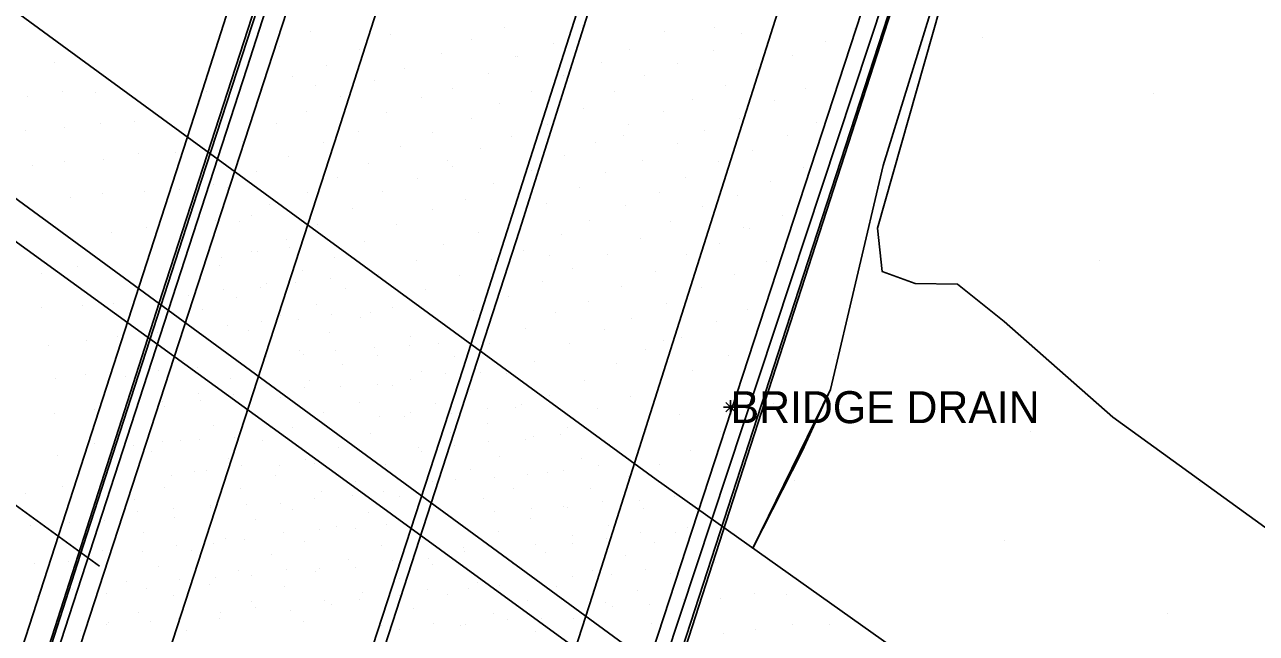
# Model space of a CAD drawing. Extents: x 0 to 1739264, y 0 to 465304.
# Drawn here: x 1738835.1 to 1738904.4, y 464692.7 to 464726.9 of the extents above; entities that cross this region are included whole.
import ezdxf

# ---------------------------------------------------------------- set-up
doc = ezdxf.new("R2010")
doc.units = 0
for name, color, linetype in [('Default', 7, 'Continuous'), ('S_Ground_SpotElevation', 7, 'Continuous'), ('S_Misc_MiscItems', 7, 'Continuous'), ('S_Terrain_Boundary', 7, 'Continuous'), ('S_Terrain_Holes', 7, 'Continuous'), ('S_Terrain_Imported_Contours', 7, 'Continuous'), ('S_Terrain_Low_Points', 7, 'Continuous'), ('S_Terrain_Major_Contours_Label', 7, 'Continuous'), ('S_Terrain_Minor_Contours', 7, 'Continuous'), ('S_Terrain_Spots', 7, 'Continuous'), ('S_Terrain_Triangles', 7, 'Continuous'), ('S_Terrain_Voids', 7, 'Continuous'), ('S_Text', 7, 'Continuous')]:
    doc.layers.add(name, color=color, linetype=linetype)

# ---------------------------------------------------------------- blocks, each defined once
blk = doc.blocks.new('POINT_DISPLAY')
at = {"layer": 'Default'}
blk.add_line((0, 0), (0, 0), dxfattribs=at)

msp = doc.modelspace()

# ---------------------------------------------------------------- linework, layer by layer
at = {"layer": 'S_Misc_MiscItems'}
for p, q in [((1738875.090081, 464705.125119), (1738874.565919, 464705.649281)), ((1738875.090081, 464705.649281), (1738874.565919, 464705.125119)), ((1738874.828, 464705.780125), (1738874.828, 464704.994275)), ((1738875.220925, 464705.3872), (1738874.435075, 464705.3872))]:
    msp.add_line(p, q, dxfattribs=at)
at = {"layer": 'S_Terrain_Boundary'}
msp.add_lwpolyline([(1739240.087209, 464422.512092), (1739204.20461, 464448.975806), (1739151.98821, 464486.847297), (1739077.545202, 464540.718299), (1739036.299199, 464570.587592), (1738998.913701, 464597.936805), (1738915.898401, 464658.026801), (1738879.6822, 464684.091499), (1738826.038202, 464723.403098), (1738785.838697, 464752.297202), (1738730.174596, 464792.732001), (1738678.937795, 464830.008598), (1738622.825002, 464870.7028), (1738578.496206, 464902.7599), (1738526.77361, 464940.2817), (1738487.876485, 464968.875201)], dxfattribs=at)
at = {"layer": 'S_Terrain_Holes'}
msp.add_lwpolyline([(1738492.982015, 464976.242099), (1738514.851095, 464960.0815), (1738563.791494, 464924.7685), (1738624.996999, 464880.339801), (1738673.015905, 464845.222999), (1738705.323293, 464821.628898), (1738726.980504, 464805.7443), (1738753.122999, 464787.077293), (1738791.7562, 464758.973594), (1738812.206201, 464744.064307), (1738838.2751, 464724.973701), (1738870.6467, 464701.313407), (1738896.6608, 464682.840995), (1738936.578298, 464654.121894), (1738968.041097, 464631.189491), (1739001.793905, 464606.514411), (1739033.507696, 464583.63401), (1739053.896306, 464568.752204), (1739082.668798, 464547.766914), (1739122.612798, 464519.166297), (1739150.551503, 464498.742286), (1739185.599386, 464473.337501), (1739245.296285, 464429.765205)], dxfattribs=at)
at = {"layer": 'S_Terrain_Imported_Contours'}
msp.add_line((1738839.318, 464696.438194), (1738826.649499, 464705.649802), dxfattribs=at)
for points in [[(1738486.786886, 464967.328601), (1738511.286214, 464949.6202), (1738544.3709, 464925.4377), (1738582.310689, 464897.903999), (1738620.877294, 464869.822101), (1738659.468999, 464841.841804), (1738694.403493, 464816.496497), (1738735.406698, 464786.775001), (1738771.038297, 464760.946204), (1738812.0253, 464731.080299), (1738852.9921, 464701.379905), (1738891.8019, 464673.129615), (1738927.017999, 464647.615485), (1738972.948697, 464614.396308), (1739021.394994, 464579.194892), (1739065.901006, 464546.893897), (1739094.060003, 464526.5232), (1739126.956991, 464502.811591), (1739168.727712, 464472.415687), (1739212.603414, 464440.554298), (1739239.28951, 464421.227393)], [(1738861.917132, 464749.554455), (1738852.728099, 464720.865302), (1738834.137899, 464663.640296), (1738810.806299, 464591.494392), (1738798.57878, 464553.775144)], [(1738807.560265, 464547.101191), (1738818.883699, 464581.650611), (1738840.7733, 464649.227912), (1738859.7717, 464707.561698), (1738871.099421, 464743.042961)], [(1738871.2811, 464741.761298), (1738862.9528, 464715.336097), (1738835.861902, 464631.717414), (1738814.1443, 464564.731208), (1738808.177672, 464546.642409)], [(1738816.833754, 464540.526168), (1738828.844899, 464576.996803), (1738841.383399, 464615.664314), (1738851.1298, 464645.487891), (1738867.0642, 464694.79), (1738880.224773, 464736.284008)]]:
    msp.add_lwpolyline(points, dxfattribs=at)
at = {"layer": 'S_Terrain_Low_Points'}
for points in [[(1738792.605864, 464561.753915), (1738808.947702, 464611.187598), (1738829.7665, 464675.843208), (1738844.662601, 464721.815192), (1738854.169417, 464751.567291)], [(1738856.4555, 464747.969505), (1738838.244399, 464692.009101), (1738826.647699, 464655.847602), (1738824.734399, 464649.915199), (1738812.578801, 464612.657905), (1738795.808896, 464560.843085)], [(1738882.8352, 464729.589896), (1738865.96384, 464677.988066), (1738852.7233, 464636.911414), (1738851.7415, 464633.401588)], [(1738885.748688, 464729.001744), (1738886.292251, 464728.345413), (1738883.4181, 464718.991294), (1738880.4518, 464706.388297), (1738878.8439, 464702.915), (1738876.083852, 464697.452527)]]:
    msp.add_lwpolyline(points, dxfattribs=at)
at = {"layer": 'S_Terrain_Major_Contours_Label'}
for points in [[(1738793.029831, 464557.898451), (1738803.9838, 464591.509406), (1738812.589898, 464618.183295), (1738822.305799, 464648.240607), (1738833.2133, 464681.803199), (1738842.84, 464711.786903), (1738850.196, 464734.470405), (1738856.340829, 464753.508813)], [(1738885.395159, 464732.452095), (1738884.2943, 464729.028999), (1738875.3401, 464701.327995), (1738857.6966, 464646.653999), (1738844.752799, 464606.659614), (1738829.9694, 464560.926002), (1738822.141572, 464536.77828)]]:
    msp.add_lwpolyline(points, dxfattribs=at)
at = {"layer": 'S_Terrain_Minor_Contours'}
msp.add_line((1738866.688, 464677.65191), (1738883.905735, 464729.730556), dxfattribs=at)
msp.add_lwpolyline([(1738835.762039, 464687.932576), (1738847.598619, 464724.443536), (1738855.882145, 464750.170609)], dxfattribs=at)
at = {"layer": 'S_Terrain_Spots'}
msp.add_lwpolyline([(1738876.083852, 464697.452527), (1738880.4518, 464706.388297), (1738883.4181, 464718.991294), (1738886.292251, 464728.345413), (1738885.754413, 464729.003456)], dxfattribs=at)
at = {"layer": 'S_Terrain_Triangles'}
for points in [[(1738793.143077, 464557.8143), (1738794.925598, 464563.221652), (1738800.413936, 464580.303997), (1738804.057897, 464591.416999), (1738810.426301, 464610.960395), (1738818.2273, 464635.285011), (1738828.789701, 464667.726112), (1738838.3903, 464697.576408), (1738845.034101, 464718.107597), (1738853.3717, 464743.659003), (1738856.448989, 464753.432112)], [(1738885.339743, 464732.493165), (1738884.4636, 464729.823402), (1738878.6737, 464712.005698), (1738871.4064, 464689.647605), (1738862.8085, 464662.946113), (1738850.8758, 464625.801398), (1738841.409499, 464596.833595), (1738830.533101, 464562.882606), (1738822.877599, 464539.516792), (1738822.019587, 464536.864414)]]:
    msp.add_lwpolyline(points, dxfattribs=at)
at = {"layer": 'S_Terrain_Voids'}
msp.add_lwpolyline([(1739013.416204, 464694.269599), (1738992.965101, 464701.439201), (1738965.663099, 464709.157493), (1738950.283803, 464712.266593), (1738937.222402, 464707.762901), (1738926.393098, 464697.901405), (1738919.4708, 464694.428107), (1738904.882501, 464698.625404), (1738896.325099, 464704.816901), (1738890.220901, 464710.206306), (1738887.592599, 464712.305305), (1738885.2014, 464712.349006), (1738883.3513, 464713.029807), (1738883.0827, 464715.465797), (1738888.3805, 464734.110099), (1738896.6555, 464759.168403), (1738900.4475, 464763.281593), (1738908.0099, 464781.7947), (1738922.6662, 464824.5549), (1738935.930204, 464865.3283), (1738941.605104, 464883.875591)], dxfattribs=at)

# ---------------------------------------------------------------- block references
at = {"layer": 'S_Ground_SpotElevation'}
for p in [(1738851.179607, 464726.509392), (1738855.691402, 464726.355522), (1738862.131007, 464726.739616), (1738866.502605, 464726.874565), (1738871.1011, 464726.510368), (1738873.915299, 464726.747596), (1738875.412105, 464726.413872), (1738881.824397, 464726.691093), (1738849.444698, 464725.70861), (1738860.247996, 464726.066215), (1738864.852397, 464725.845085), (1738880.143001, 464725.964409), (1738889.020493, 464726.170879), (1738853.943706, 464725.52819), (1738858.583797, 464725.288566), (1738862.728299, 464725.105994), (1738862.8231, 464725.117668), (1738869.120799, 464725.542473), (1738873.846797, 464725.436577), (1738878.2886, 464725.153313), (1738836.769603, 464724.795803), (1738852.062007, 464724.60601), (1738856.474101, 464724.429985), (1738867.554195, 464724.78582), (1738871.831599, 464724.749687), (1738876.309795, 464724.395073), (1738850.187801, 464724.015983), (1738854.782298, 464723.794975), (1738861.199397, 464724.168388), (1738865.429805, 464724.061394), (1738869.991603, 464724.038566), (1738880.997295, 464724.23217), (1738835.254101, 464722.880001), (1738837.217388, 464723.139706), (1738839.120586, 464723.106701), (1738845.317094, 464723.150189), (1738848.490001, 464723.263603), (1738851.4472, 464723.516395), (1738852.876201, 464722.85778), (1738859.178706, 464723.346672), (1738863.619594, 464723.148613), (1738868.296596, 464723.178581), (1738874.525005, 464723.502922), (1738879.062099, 464723.305595), (1738898.626008, 464723.063519), (1738857.461406, 464722.796379), (1738861.799998, 464722.477409), (1738866.551799, 464722.17382), (1738872.693599, 464722.692802), (1738877.322505, 464722.64019), (1738850.976298, 464722.030388), (1738855.455699, 464721.945305), (1738860.261607, 464721.61541), (1738871.044704, 464722.040581), (1738875.313808, 464721.632683), (1738880.308699, 464721.944007), (1738835.138408, 464720.949398), (1738837.352306, 464721.104611), (1738839.398693, 464721.357205), (1738841.268291, 464721.448605), (1738849.293208, 464721.331474), (1738853.884105, 464720.911064), (1738858.0666, 464720.828667), (1738864.546001, 464721.276665), (1738869.059703, 464721.287285), (1738873.3334, 464720.977775), (1738879.685405, 464721.428703), (1738847.391307, 464720.331901), (1738851.893306, 464720.288505), (1738862.521098, 464720.609367), (1738867.229594, 464720.30468), (1738868.8017, 464720.668601), (1738871.831004, 464720.217522), (1738878.050304, 464720.664299), (1738841.485393, 464719.641201), (1738843.577404, 464719.722805), (1738849.956599, 464719.519279), (1738856.261607, 464720.066521), (1738860.745097, 464719.950615), (1738865.498302, 464719.547966), (1738876.053905, 464719.826591), (1738835.5312, 464718.97131), (1738837.33601, 464719.186505), (1738839.549999, 464719.352108), (1738854.477397, 464719.098564), (1738858.908, 464719.285193), (1738859.1972, 464718.904899), (1738863.645595, 464718.711906), (1738869.875102, 464719.248894), (1738874.138393, 464719.194267), (1738878.942699, 464718.882072), (1738848.168697, 464718.675102), (1738852.713405, 464718.291008), (1738857.213695, 464718.2658), (1738867.794704, 464718.614006), (1738872.307002, 464718.337517), (1738877.057994, 464718.083977), (1738839.461895, 464717.401104), (1738841.827801, 464717.498104), (1738843.825298, 464717.656399), (1738845.757213, 464717.943402), (1738846.5115, 464717.73809), (1738851.038798, 464717.468376), (1738855.249095, 464717.536491), (1738861.511394, 464717.993584), (1738866.305202, 464717.747185), (1738870.806102, 464717.477898), (1738875.240596, 464717.324089), (1738883.760194, 464717.70097), (1738837.704296, 464717.188198), (1738848.904704, 464716.820122), (1738859.927608, 464717.065117), (1738864.449702, 464716.82299), (1738868.929698, 464716.722771), (1738873.240199, 464716.679863), (1738847.872295, 464716.16), (1738853.557307, 464716.562919), (1738858.070598, 464716.524101), (1738862.421199, 464716.282768), (1738877.727397, 464716.18267), (1738841.970501, 464715.511898), (1738844.018291, 464715.691006), (1738845.862591, 464715.895199), (1738847.196101, 464715.859611), (1738851.587596, 464715.668205), (1738856.048793, 464715.665398), (1738860.629298, 464715.228508), (1738866.864497, 464715.908073), (1738871.434795, 464715.811088), (1738875.5377, 464715.513007), (1738875.903194, 464715.424309), (1738839.979686, 464715.188809), (1738849.833308, 464714.832085), (1738854.207194, 464714.7033), (1738865.318294, 464715.124382), (1738869.749904, 464714.860222), (1738874.214793, 464714.59832), (1738847.879207, 464714.168388), (1738848.184093, 464714.158612), (1738849.996013, 464714.387799), (1738858.687099, 464714.534294), (1738863.183406, 464714.225517), (1738864.6091, 464713.898001), (1738867.892802, 464713.959282), (1738872.320293, 464713.957573), (1738838.077404, 464713.283108), (1738842.054302, 464713.671398), (1738844.188488, 464713.780606), (1738846.052104, 464713.341484), (1738846.180401, 464713.831799), (1738852.539699, 464713.808281), (1738857.151393, 464713.627067), (1738861.345805, 464713.670769), (1738865.906505, 464713.205009), (1738876.831905, 464713.602714), (1738895.591599, 464713.632916), (1738836.069286, 464712.911511), (1738850.762706, 464713.079765), (1738852.302105, 464712.634808), (1738855.040294, 464712.868767), (1738859.550197, 464712.824272), (1738864.2653, 464712.472771), (1738870.574901, 464712.996513), (1738875.050304, 464712.868278), (1738846.276989, 464711.987408), (1738848.382305, 464712.097409), (1738848.729304, 464712.326774), (1738850.366985, 464712.381008), (1738853.176295, 464712.065605), (1738857.672298, 464711.997673), (1738868.666698, 464712.16552), (1738873.195094, 464712.147392), (1738838.389599, 464711.091198), (1738840.093487, 464711.21751), (1738844.329509, 464711.691403), (1738847.012508, 464711.567314), (1738851.530894, 464711.13781), (1738862.346004, 464711.633415), (1738866.849696, 464711.314323), (1738871.2382, 464711.239616), (1738836.059307, 464710.988903), (1738845.094096, 464710.894401), (1738849.489604, 464710.542595), (1738852.389904, 464710.6143), (1738853.999797, 464710.427666), (1738854.539287, 464710.736904), (1738855.814296, 464711.019707), (1738860.3464, 464710.850578), (1738864.950496, 464710.703972), (1738869.225993, 464710.385918), (1738875.787501, 464710.908989), (1738846.531109, 464709.963406), (1738847.6804, 464709.706108), (1738848.405987, 464710.230999), (1738850.505413, 464710.322811), (1738858.462505, 464710.167717), (1738863.270305, 464709.829521), (1738867.715297, 464709.759209), (1738874.039607, 464710.231804), (1738838.602703, 464709.139309), (1738840.344311, 464709.37991), (1738842.596203, 464709.594403), (1738852.246699, 464709.590263), (1738856.824596, 464709.370781), (1738871.0467, 464709.116095), (1738872.057002, 464709.328972), (1738836.461803, 464708.879208), (1738845.878398, 464708.905205), (1738850.587596, 464708.577019), (1738850.797497, 464708.333111), (1738852.601085, 464708.573208), (1738854.781109, 464708.718807), (1738854.9761, 464708.300712), (1738856.764995, 464708.836209), (1738858.399303, 464708.964504), (1738861.279796, 464708.952568), (1738865.7756, 464708.955009), (1738870.017894, 464708.617912), (1738874.729198, 464708.313164), (1738880.6297, 464708.374798), (1738844.019206, 464708.021416), (1738844.831402, 464707.613308), (1738848.571696, 464708.000908), (1738848.688396, 464708.228802), (1738852.984096, 464707.806206), (1738859.294597, 464708.219902), (1738863.780406, 464707.946403), (1738868.425807, 464707.855278), (1738836.8531, 464706.986111), (1738838.526104, 464707.200299), (1738840.783611, 464707.125012), (1738842.664196, 464707.430905), (1738846.662395, 464707.00811), (1738856.839, 464706.960507), (1738857.4183, 464707.407219), (1738858.809612, 464707.283306), (1738860.737194, 464707.317303), (1738862.238795, 464707.289299), (1738872.702205, 464707.443474), (1738850.828106, 464706.497906), (1738851.134303, 464706.896965), (1738852.876995, 464706.575009), (1738854.952099, 464706.669506), (1738855.784495, 464706.62957), (1738860.172801, 464706.385979), (1738866.617107, 464706.872002), (1738870.891093, 464706.82238), (1738875.344401, 464706.464165), (1738842.867992, 464705.684506), (1738844.898494, 464706.172722), (1738844.997814, 464705.783901), (1738846.845989, 464706.083798), (1738849.522304, 464705.905571), (1738853.962901, 464705.673515), (1738858.229304, 464705.58062), (1738863.074291, 464705.549298), (1738864.631801, 464706.030693), (1738869.209407, 464705.964165), (1738877.212901, 464705.574196), (1738836.789196, 464705.048199), (1738839.009014, 464705.241604), (1738840.83189, 464705.518505), (1738843.002299, 464705.432121), (1738847.575908, 464705.197197), (1738851.939006, 464705.069511), (1738855.098613, 464704.884411), (1738856.504802, 464704.835319), (1738856.805309, 464705.082699), (1738859.145397, 464705.0126), (1738861.132305, 464705.324307), (1738862.740794, 464705.363518), (1738867.318095, 464705.311882), (1738871.965495, 464704.998405), (1738845.709193, 464704.378776), (1738848.932689, 464704.226803), (1738850.171504, 464704.262199), (1738861.159007, 464704.487175), (1738865.664699, 464704.260612), (1738842.885113, 464703.467205), (1738843.857402, 464703.517692), (1738844.931011, 464703.578808), (1738846.9239, 464703.670712), (1738848.466807, 464703.529411), (1738854.5787, 464703.90728), (1738859.079295, 464703.937492), (1738861.230785, 464703.468502), (1738863.299206, 464703.5462), (1738863.761806, 464703.732414), (1738865.266704, 464703.85191), (1738870.118007, 464704.130607), (1738874.284007, 464704.023003), (1738891.716203, 464704.039471), (1738839.050915, 464703.324902), (1738841.218914, 464703.25021), (1738842.266795, 464702.873772), (1738852.771602, 464703.136406), (1738857.241985, 464703.114605), (1738857.4575, 464702.914116), (1738859.311199, 464703.217312), (1738868.030604, 464703.293388), (1738872.581905, 464702.976921), (1738836.951885, 464702.673809), (1738846.555904, 464702.511711), (1738847.288585, 464702.122509), (1738849.420208, 464702.093899), (1738850.904094, 464702.452812), (1738851.394787, 464702.21751), (1738855.403499, 464702.155022), (1738861.799403, 464702.613579), (1738866.422206, 464702.473381), (1738867.412914, 464702.102505), (1738870.831203, 464702.150688), (1738841.287395, 464701.479412), (1738843.378399, 464701.523709), (1738844.665996, 464701.755363), (1738845.359295, 464701.84251), (1738849.205699, 464701.518303), (1738860.165996, 464701.907402), (1738861.514995, 464701.450802), (1738863.417797, 464701.592098), (1738864.541606, 464701.704277), (1738865.450207, 464701.799511), (1738869.074107, 464701.479912), (1738837.244793, 464700.914105), (1738839.351299, 464701.051708), (1738842.985606, 464700.859794), (1738847.237804, 464700.798881), (1738853.733699, 464701.22448), (1738858.077693, 464701.189323), (1738859.355205, 464701.332897), (1738862.635799, 464700.79998), (1738866.968806, 464700.830192), (1738873.574199, 464701.241691), (1738878.438096, 464701.24992), (1738901.204896, 464701.149273), (1738835.172497, 464700.511608), (1738841.303996, 464700.177666), (1738851.442089, 464700.27351), (1738851.790706, 464700.631523), (1738853.553814, 464700.399502), (1738855.323406, 464700.659405), (1738856.196803, 464700.382011), (1738860.924998, 464700.250175), (1738867.611706, 464700.064511), (1738869.703594, 464700.1591), (1738871.696605, 464700.374199), (1738841.434307, 464699.533703), (1738843.501812, 464699.696499), (1738845.542995, 464699.833671), (1738845.579601, 464699.769299), (1738847.612407, 464699.919705), (1738849.503795, 464699.94421), (1738850.158794, 464699.602775), (1738854.428905, 464699.461784), (1738861.559795, 464699.512707), (1738863.631298, 464699.689404), (1738865.403102, 464699.79998), (1738865.657207, 464699.759701), (1738869.924602, 464699.689995), (1738835.449901, 464698.717709), (1738837.628185, 464698.919903), (1738839.627086, 464699.021206), (1738843.561397, 464699.189323), (1738848.103999, 464699.073173), (1738852.628505, 464698.65258), (1738855.4575, 464698.803005), (1738859.119899, 464699.251213), (1738863.576594, 464699.095695), (1738867.932597, 464698.742912), (1738872.377101, 464698.603264), (1738841.799297, 464698.319694), (1738846.427394, 464697.98632), (1738847.45869, 464697.917309), (1738849.650402, 464698.357403), (1738851.719707, 464698.4781), (1738853.7057, 464698.557507), (1738857.227306, 464698.339897), (1738861.794994, 464698.388115), (1738865.918193, 464698.182121), (1738867.841686, 464698.017605), (1738869.764385, 464698.308209), (1738871.747509, 464698.334011), (1738839.483104, 464697.32481), (1738840.032497, 464697.477714), (1738841.761394, 464697.2617), (1738843.672313, 464697.580898), (1738844.498103, 464697.296318), (1738845.738811, 464697.691204), (1738850.871898, 464697.843803), (1738855.192104, 464697.577873), (1738859.809505, 464697.50872), (1738859.855297, 464697.267803), (1738863.871807, 464697.674298), (1738865.92979, 464697.739605), (1738870.557994, 464697.792595), (1738890.263001, 464697.900128), (1738835.651012, 464696.597805), (1738837.559612, 464696.686001), (1738848.968898, 464697.087273), (1738853.351695, 464696.807304), (1738855.803386, 464696.764309), (1738857.807415, 464696.879208), (1738858.064998, 464696.555412), (1738862.547603, 464696.569206), (1738864.411998, 464697.194816), (1738868.893794, 464697.032585), (1738874.002697, 464696.634609), (1738842.621501, 464696.398491), (1738847.163402, 464696.191399), (1738847.882702, 464695.924404), (1738849.811687, 464696.253811), (1738851.498607, 464696.118584), (1738851.699505, 464696.285809), (1738853.711101, 464696.375012), (1738865.946514, 464695.86871), (1738867.078899, 464696.20977), (1738868.107891, 464695.983807), (1738870.041607, 464696.277401), (1738871.426005, 464696.008903), (1738871.986706, 464696.473705), (1738840.812602, 464695.597893), (1738841.969005, 464695.156307), (1738843.791607, 464695.713009), (1738845.5227, 464695.409111), (1738845.827007, 464695.815197), (1738849.702998, 464695.283867), (1738856.184703, 464695.765007), (1738860.071911, 464695.170803), (1738860.605693, 464695.545708), (1738861.820598, 464695.349804), (1738865.015498, 464695.306816), (1738835.8531, 464694.745007), (1738837.778393, 464695.105404), (1738839.1795, 464694.903923), (1738839.734295, 464694.919903), (1738843.505397, 464694.778007), (1738847.876094, 464694.437981), (1738851.960888, 464694.505108), (1738853.949596, 464694.589703), (1738854.143504, 464694.968986), (1738856.18629, 464694.78001), (1738857.763592, 464695.104412), (1738858.898494, 464694.828667), (1738863.386302, 464694.52288), (1738869.581203, 464695.073173), (1738872.169414, 464694.536709), (1738874.231304, 464694.615902), (1738876.185985, 464694.915508), (1738877.971813, 464694.855007), (1738841.534007, 464693.823906), (1738846.108196, 464693.83981), (1738848.122204, 464694.131298), (1738850.075786, 464693.923397), (1738852.345302, 464694.280083), (1738856.977702, 464694.056999), (1738861.459605, 464693.764091), (1738867.7662, 464694.400566), (1738868.159191, 464694.159802), (1738870.280315, 464694.2608), (1738899.411195, 464693.770367), (1738839.694804, 464693.141594), (1738839.818187, 464693.288403), (1738842.187298, 464693.300305), (1738843.781414, 464693.515499), (1738846.077205, 464693.517998), (1738850.7783, 464693.336784), (1738855.160594, 464693.088615), (1738858.112804, 464693.1945), (1738859.620097, 464693.115105), (1738859.899608, 464693.173611), (1738862.271312, 464693.434506), (1738864.203594, 464693.492108), (1738866.011607, 464693.516716), (1738870.365794, 464693.209282), (1738878.329998, 464693.155102), (1738880.36491, 464693.168209), (1738838.232891, 464692.8027), (1738844.223796, 464692.828911), (1738856.181591, 464692.863705), (1738863.864604, 464692.783806), (1738874.45039, 464692.674008), (1738876.228008, 464692.84811)]:
    msp.add_blockref('POINT_DISPLAY', p, dxfattribs=at)

# ---------------------------------------------------------------- texts
at = {"layer": 'S_Text'}
msp.add_text('BRIDGE DRAIN', height=1.8, dxfattribs=at).set_placement((1738874.828, 464704.4872))

doc.saveas('drawing.dxf')
